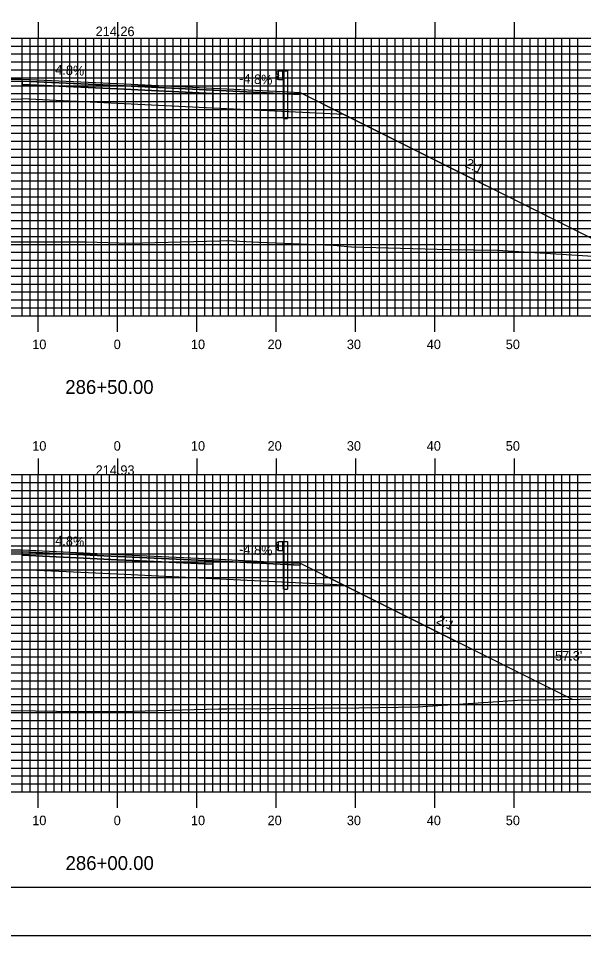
# Model space of a CAD drawing. Extents: x 1812554 to 1812897, y 442591 to 442811.
# Drawn here: x 1812707.4 to 1812778.7, y 442590.5 to 442706.2 of the extents above; entities that cross this region are included whole.
import ezdxf

# ---------------------------------------------------------------- set-up
doc = ezdxf.new("R2010")
doc.units = 0
for name, color, linetype in [('ANNOTATION', 7, 'Continuous'), ('BORDER', 7, 'Continuous'), ('D_Guardrail_Beam_Rt', 7, 'Continuous'), ('D_Roadway_Centerline', 7, 'Continuous'), ('D_Roadway_Centerline_Text', 7, 'Continuous'), ('D_Roadway_Edge_Shoulder', 7, 'Continuous'), ('D_Roadway_Edge_TW', 7, 'Continuous'), ('D_Roadway_Pavement', 7, 'Continuous'), ('D_Roadway_SlopeLines', 7, 'Continuous'), ('D_Roadway_SubGrade', 7, 'Continuous'), ('D_Text_Standard', 7, 'Continuous'), ('H_V ANNOTATION', 7, 'Continuous'), ('MAJOR', 7, 'Continuous'), ('MINOR', 7, 'Continuous'), ('PLOT BOUNDARY', 7, 'Continuous'), ('S_Roadway_Centerline', 7, 'Continuous')]:
    doc.layers.add(name, color=color, linetype=linetype)

msp = doc.modelspace()

# ---------------------------------------------------------------- linework, layer by layer
at = {"layer": 'BORDER'}
msp.add_lwpolyline([(1812570.34, 442596.67), (1812890.34, 442596.67), (1812890.34, 442806.67), (1812570.34, 442806.67)], close=True, dxfattribs=at)
at = {"layer": 'D_Guardrail_Beam_Rt'}
for p, q in [((1812740.12, 442699.45), (1812739.98, 442699.35)), ((1812740.21, 442699.47), (1812740.14, 442699.45)), ((1812740.21, 442699.55), (1812740.9, 442699.55)), ((1812740.21, 442698.39), (1812740.21, 442699.55)), ((1812740.73, 442699.55), (1812740.73, 442698.39)), ((1812740.84, 442699.55), (1812740.84, 442698.39)), ((1812740.9, 442699.55), (1812741.37, 442699.55)), ((1812740.9, 442699.55), (1812740.9, 442698.39)), ((1812741.37, 442699.55), (1812741.37, 442693.55)), ((1812739.98, 442699.2), (1812740.17, 442699.07)), ((1812740.17, 442698.87), (1812739.98, 442698.73)), ((1812739.98, 442698.59), (1812740.12, 442698.49)), ((1812740.14, 442698.48), (1812740.21, 442698.47)), ((1812740.21, 442699), (1812740.21, 442698.93)), ((1812740.9, 442698.39), (1812740.21, 442698.39)), ((1812740.88, 442693.55), (1812740.88, 442698.39)), ((1812740.88, 442693.55), (1812741.37, 442693.55)), ((1812740.12, 442640.11), (1812739.98, 442640.01)), ((1812739.98, 442639.87), (1812740.17, 442639.73)), ((1812740.17, 442639.53), (1812739.98, 442639.4)), ((1812740.21, 442640.13), (1812740.14, 442640.12)), ((1812740.21, 442640.22), (1812740.9, 442640.22)), ((1812740.21, 442639.05), (1812740.21, 442640.22)), ((1812740.21, 442639.67), (1812740.21, 442639.6)), ((1812740.73, 442640.22), (1812740.73, 442639.05)), ((1812740.84, 442640.22), (1812740.84, 442639.05)), ((1812740.9, 442640.22), (1812741.37, 442640.22)), ((1812740.9, 442640.22), (1812740.9, 442639.05)), ((1812741.37, 442640.22), (1812741.37, 442634.22)), ((1812739.98, 442639.25), (1812740.12, 442639.15)), ((1812740.14, 442639.15), (1812740.21, 442639.13)), ((1812740.9, 442639.05), (1812740.21, 442639.05)), ((1812740.88, 442634.22), (1812740.88, 442639.05)), ((1812740.88, 442634.22), (1812741.37, 442634.22))]:
    msp.add_line(p, q, dxfattribs=at)
for centre, major_axis, start_param, end_param in [((1812740.15, 442699.41), (-0.0417, 0), 4.907132, 5.323254), ((1812740.03, 442699.28), (-0.0877, 0), 5.323254, 7.243116), ((1812740.03, 442698.66), (-0.0877, 0), 5.323254, 7.243116), ((1812740.15, 442698.52), (-0.0417, 0), 0.959931, 1.376053), ((1812740.13, 442699), (0.0789, 0), 0, 0.959931), ((1812740.13, 442698.93), (0.0789, 0), 5.323254, 6.283185), ((1812740.03, 442639.94), (-0.0877, 0), 5.323254, 7.243116), ((1812740.03, 442639.33), (-0.0877, 0), 5.323254, 7.243116), ((1812740.15, 442640.08), (-0.0417, 0), 4.907132, 5.323254), ((1812740.13, 442639.67), (0.0789, 0), 0, 0.959931), ((1812740.13, 442639.6), (0.0789, 0), 5.323254, 6.283185), ((1812740.15, 442639.19), (-0.0417, 0), 0.959931, 1.376053)]:
    msp.add_ellipse(centre, major_axis=major_axis, ratio=0.995501, start_param=start_param, end_param=end_param, dxfattribs=at)
at = {"layer": 'D_Roadway_Centerline'}
for points in [[(1812656.82, 442678.23), (1812691.73, 442695.68), (1812696.94, 442698.28), (1812699.94, 442698.34), (1812707.94, 442698.5), (1812719.94, 442697.93), (1812731.94, 442697.35), (1812739.94, 442696.97), (1812742.94, 442696.82), (1812748.47, 442694.06), (1812784.48, 442676.06)], [(1812656.53, 442618.74), (1812691.73, 442636.34), (1812696.94, 442638.95), (1812699.94, 442639.01), (1812707.94, 442639.17), (1812719.94, 442638.59), (1812731.94, 442638.02), (1812739.94, 442637.63), (1812742.94, 442637.49), (1812748.47, 442634.72), (1812777.24, 442620.34)]]:
    msp.add_lwpolyline(points, dxfattribs=at)
at = {"layer": 'D_Roadway_Edge_Shoulder'}
for points in [[(1812707.94, 442698.5), (1812699.94, 442698.34), (1812699.94, 442698.34), (1812696.94, 442698.28), (1812696.94, 442698.03), (1812707.94, 442698.25)], [(1812731.94, 442697.35), (1812739.94, 442696.97), (1812739.94, 442696.97), (1812742.94, 442696.82), (1812742.94, 442696.57), (1812731.94, 442697.1)], [(1812707.94, 442639.17), (1812699.94, 442639.01), (1812699.94, 442639.01), (1812696.94, 442638.95), (1812696.94, 442638.7), (1812707.94, 442638.92)], [(1812731.94, 442638.02), (1812739.94, 442637.63), (1812739.94, 442637.63), (1812742.94, 442637.49), (1812742.94, 442637.24), (1812731.94, 442637.77)]]:
    msp.add_lwpolyline(points, close=True, dxfattribs=at)
at = {"layer": 'D_Roadway_Edge_TW'}
for points in [[(1812707.94, 442698.25), (1812707.94, 442698.5), (1812719.94, 442697.93), (1812731.94, 442697.35), (1812731.94, 442697.1), (1812719.94, 442697.68)], [(1812707.94, 442638.92), (1812707.94, 442639.17), (1812719.94, 442638.59), (1812731.94, 442638.02), (1812731.94, 442637.77), (1812719.94, 442638.34)]]:
    msp.add_lwpolyline(points, close=True, dxfattribs=at)
at = {"layer": 'D_Roadway_Pavement'}
for points in [[(1812707.94, 442697.84), (1812707.94, 442698.25), (1812719.94, 442697.68), (1812731.94, 442697.1), (1812731.94, 442696.69), (1812719.94, 442697.26)], [(1812707.94, 442638.5), (1812707.94, 442638.92), (1812719.94, 442638.34), (1812731.94, 442637.77), (1812731.94, 442637.35), (1812719.94, 442637.93)]]:
    msp.add_lwpolyline(points, close=True, dxfattribs=at)
for points in [[(1812707.94, 442698.25), (1812707.94, 442697.84)], [(1812731.94, 442697.1), (1812731.94, 442696.69)], [(1812707.94, 442638.92), (1812707.94, 442638.5)], [(1812731.94, 442637.77), (1812731.94, 442637.35)]]:
    msp.add_lwpolyline(points, dxfattribs=at)
at = {"layer": 'D_Roadway_SlopeLines'}
for points in [[(1812742.94, 442696.82), (1812784.48, 442676.06)], [(1812742.94, 442637.49), (1812777.24, 442620.34)]]:
    msp.add_lwpolyline(points, dxfattribs=at)
at = {"layer": 'D_Roadway_SubGrade'}
for points in [[(1812707.94, 442697.84), (1812707.94, 442698.25), (1812696.94, 442698.03), (1812696.94, 442698.28), (1812691.73, 442695.68), (1812707.94, 442696)], [(1812707.94, 442696), (1812707.94, 442698.25), (1812707.94, 442697.84), (1812719.94, 442697.26), (1812731.94, 442696.69), (1812731.94, 442697.1), (1812731.94, 442694.85), (1812719.94, 442695.43)], [(1812731.94, 442696.69), (1812731.94, 442697.1), (1812742.94, 442696.57), (1812742.94, 442696.82), (1812748.47, 442694.06), (1812731.94, 442694.85)], [(1812707.94, 442638.5), (1812707.94, 442638.92), (1812696.94, 442638.7), (1812696.94, 442638.95), (1812691.73, 442636.34), (1812707.94, 442636.67)], [(1812707.94, 442636.67), (1812707.94, 442638.92), (1812707.94, 442638.5), (1812719.94, 442637.93), (1812731.94, 442637.35), (1812731.94, 442637.77), (1812731.94, 442635.52), (1812719.94, 442636.09)], [(1812731.94, 442637.35), (1812731.94, 442637.77), (1812742.94, 442637.24), (1812742.94, 442637.49), (1812748.47, 442634.72), (1812731.94, 442635.52)]]:
    msp.add_lwpolyline(points, close=True, dxfattribs=at)
at = {"layer": 'MAJOR'}
for p, q in [((1812709.94, 442705.67), (1812709.94, 442703.67)), ((1812719.94, 442705.67), (1812719.94, 442703.67)), ((1812729.94, 442705.67), (1812729.94, 442703.67)), ((1812739.94, 442705.67), (1812739.94, 442703.67)), ((1812749.94, 442705.67), (1812749.94, 442703.67)), ((1812759.94, 442705.67), (1812759.94, 442703.67)), ((1812769.94, 442705.67), (1812769.94, 442703.67)), ((1812579.94, 442703.67), (1812859.94, 442703.67)), ((1812579.94, 442703.67), (1812859.94, 442703.67)), ((1812709.94, 442668.67), (1812709.94, 442703.67)), ((1812719.94, 442668.67), (1812719.94, 442703.67)), ((1812729.94, 442668.67), (1812729.94, 442703.67)), ((1812739.94, 442668.67), (1812739.94, 442703.67)), ((1812749.94, 442668.67), (1812749.94, 442703.67)), ((1812759.94, 442668.67), (1812759.94, 442703.67)), ((1812769.94, 442668.67), (1812769.94, 442703.67)), ((1812579.94, 442698.67), (1812859.94, 442698.67)), ((1812579.94, 442693.67), (1812859.94, 442693.67)), ((1812579.94, 442688.67), (1812859.94, 442688.67)), ((1812579.94, 442683.67), (1812859.94, 442683.67)), ((1812579.94, 442678.67), (1812859.94, 442678.67)), ((1812579.94, 442673.67), (1812859.94, 442673.67)), ((1812579.94, 442668.67), (1812859.94, 442668.67)), ((1812579.94, 442668.67), (1812859.94, 442668.67)), ((1812709.94, 442666.66), (1812709.94, 442668.67)), ((1812719.94, 442666.66), (1812719.94, 442668.67)), ((1812729.94, 442666.66), (1812729.94, 442668.67)), ((1812739.94, 442666.66), (1812739.94, 442668.67)), ((1812749.94, 442666.66), (1812749.94, 442668.67)), ((1812759.94, 442666.66), (1812759.94, 442668.67)), ((1812769.94, 442666.66), (1812769.94, 442668.67)), ((1812709.94, 442650.67), (1812709.94, 442648.67)), ((1812719.94, 442650.67), (1812719.94, 442648.67)), ((1812729.94, 442650.67), (1812729.94, 442648.67)), ((1812739.94, 442650.67), (1812739.94, 442648.67)), ((1812749.94, 442650.67), (1812749.94, 442648.67)), ((1812759.94, 442650.67), (1812759.94, 442648.67)), ((1812769.94, 442650.67), (1812769.94, 442648.67)), ((1812579.94, 442648.67), (1812859.94, 442648.67)), ((1812579.94, 442648.67), (1812859.94, 442648.67)), ((1812709.94, 442608.67), (1812709.94, 442648.67)), ((1812719.94, 442608.67), (1812719.94, 442648.67)), ((1812729.94, 442608.67), (1812729.94, 442648.67)), ((1812739.94, 442608.67), (1812739.94, 442648.67)), ((1812749.94, 442608.67), (1812749.94, 442648.67)), ((1812759.94, 442608.67), (1812759.94, 442648.67)), ((1812769.94, 442608.67), (1812769.94, 442648.67)), ((1812579.94, 442643.67), (1812859.94, 442643.67)), ((1812579.94, 442638.67), (1812859.94, 442638.67)), ((1812579.94, 442633.67), (1812859.94, 442633.67)), ((1812579.94, 442628.67), (1812859.94, 442628.67)), ((1812579.94, 442623.67), (1812859.94, 442623.67)), ((1812579.94, 442618.67), (1812859.94, 442618.67)), ((1812579.94, 442613.67), (1812859.94, 442613.67)), ((1812579.94, 442608.67), (1812859.94, 442608.67)), ((1812579.94, 442608.67), (1812859.94, 442608.67)), ((1812709.94, 442606.66), (1812709.94, 442608.67)), ((1812719.94, 442606.66), (1812719.94, 442608.67)), ((1812729.94, 442606.66), (1812729.94, 442608.67)), ((1812739.94, 442606.66), (1812739.94, 442608.67)), ((1812749.94, 442606.66), (1812749.94, 442608.67)), ((1812759.94, 442606.66), (1812759.94, 442608.67)), ((1812769.94, 442606.66), (1812769.94, 442608.67))]:
    msp.add_line(p, q, dxfattribs=at)
at = {"layer": 'MINOR'}
for p, q in [((1812707.94, 442668.67), (1812707.94, 442703.67)), ((1812708.94, 442668.67), (1812708.94, 442703.67)), ((1812710.94, 442668.67), (1812710.94, 442703.67)), ((1812711.94, 442668.67), (1812711.94, 442703.67)), ((1812712.94, 442668.67), (1812712.94, 442703.67)), ((1812713.94, 442668.67), (1812713.94, 442703.67)), ((1812714.94, 442668.67), (1812714.94, 442703.67)), ((1812715.94, 442668.67), (1812715.94, 442703.67)), ((1812716.94, 442668.67), (1812716.94, 442703.67)), ((1812717.94, 442668.67), (1812717.94, 442703.67)), ((1812718.94, 442668.67), (1812718.94, 442703.67)), ((1812720.94, 442668.67), (1812720.94, 442703.67)), ((1812721.94, 442668.67), (1812721.94, 442703.67)), ((1812722.94, 442668.67), (1812722.94, 442703.67)), ((1812723.94, 442668.67), (1812723.94, 442703.67)), ((1812724.94, 442668.67), (1812724.94, 442703.67)), ((1812725.94, 442668.67), (1812725.94, 442703.67)), ((1812726.94, 442668.67), (1812726.94, 442703.67)), ((1812727.94, 442668.67), (1812727.94, 442703.67)), ((1812728.94, 442668.67), (1812728.94, 442703.67)), ((1812730.94, 442668.67), (1812730.94, 442703.67)), ((1812731.94, 442668.67), (1812731.94, 442703.67)), ((1812732.94, 442668.67), (1812732.94, 442703.67)), ((1812733.94, 442668.67), (1812733.94, 442703.67)), ((1812734.94, 442668.67), (1812734.94, 442703.67)), ((1812735.94, 442668.67), (1812735.94, 442703.67)), ((1812736.94, 442668.67), (1812736.94, 442703.67)), ((1812737.94, 442668.67), (1812737.94, 442703.67)), ((1812738.94, 442668.67), (1812738.94, 442703.67)), ((1812740.94, 442668.67), (1812740.94, 442703.67)), ((1812741.94, 442668.67), (1812741.94, 442703.67)), ((1812742.94, 442668.67), (1812742.94, 442703.67)), ((1812743.94, 442668.67), (1812743.94, 442703.67)), ((1812744.94, 442668.67), (1812744.94, 442703.67)), ((1812745.94, 442668.67), (1812745.94, 442703.67)), ((1812746.94, 442668.67), (1812746.94, 442703.67)), ((1812747.94, 442668.67), (1812747.94, 442703.67)), ((1812748.94, 442668.67), (1812748.94, 442703.67)), ((1812750.94, 442668.67), (1812750.94, 442703.67)), ((1812751.94, 442668.67), (1812751.94, 442703.67)), ((1812752.94, 442668.67), (1812752.94, 442703.67)), ((1812753.94, 442668.67), (1812753.94, 442703.67)), ((1812754.94, 442668.67), (1812754.94, 442703.67)), ((1812755.94, 442668.67), (1812755.94, 442703.67)), ((1812756.94, 442668.67), (1812756.94, 442703.67)), ((1812757.94, 442668.67), (1812757.94, 442703.67)), ((1812758.94, 442668.67), (1812758.94, 442703.67)), ((1812760.94, 442668.67), (1812760.94, 442703.67)), ((1812761.94, 442668.67), (1812761.94, 442703.67)), ((1812762.94, 442668.67), (1812762.94, 442703.67)), ((1812763.94, 442668.67), (1812763.94, 442703.67)), ((1812764.94, 442668.67), (1812764.94, 442703.67)), ((1812765.94, 442668.67), (1812765.94, 442703.67)), ((1812766.94, 442668.67), (1812766.94, 442703.67)), ((1812767.94, 442668.67), (1812767.94, 442703.67)), ((1812768.94, 442668.67), (1812768.94, 442703.67)), ((1812770.94, 442668.67), (1812770.94, 442703.67)), ((1812771.94, 442668.67), (1812771.94, 442703.67)), ((1812772.94, 442668.67), (1812772.94, 442703.67)), ((1812773.94, 442668.67), (1812773.94, 442703.67)), ((1812774.94, 442668.67), (1812774.94, 442703.67)), ((1812775.94, 442668.67), (1812775.94, 442703.67)), ((1812776.94, 442668.67), (1812776.94, 442703.67)), ((1812777.94, 442668.67), (1812777.94, 442703.67)), ((1812579.94, 442702.67), (1812859.94, 442702.67)), ((1812579.94, 442701.67), (1812859.94, 442701.67)), ((1812579.94, 442700.67), (1812859.94, 442700.67)), ((1812579.94, 442699.67), (1812859.94, 442699.67)), ((1812579.94, 442697.67), (1812859.94, 442697.67)), ((1812579.94, 442696.67), (1812859.94, 442696.67)), ((1812579.94, 442695.67), (1812859.94, 442695.67)), ((1812579.94, 442694.67), (1812859.94, 442694.67)), ((1812579.94, 442692.67), (1812859.94, 442692.67)), ((1812579.94, 442691.67), (1812859.94, 442691.67)), ((1812579.94, 442690.67), (1812859.94, 442690.67)), ((1812579.94, 442689.67), (1812859.94, 442689.67)), ((1812579.94, 442687.67), (1812859.94, 442687.67)), ((1812579.94, 442686.67), (1812859.94, 442686.67)), ((1812579.94, 442685.67), (1812859.94, 442685.67)), ((1812579.94, 442684.67), (1812859.94, 442684.67)), ((1812579.94, 442682.67), (1812859.94, 442682.67)), ((1812579.94, 442681.67), (1812859.94, 442681.67)), ((1812579.94, 442680.67), (1812859.94, 442680.67)), ((1812579.94, 442679.67), (1812859.94, 442679.67)), ((1812579.94, 442677.67), (1812859.94, 442677.67)), ((1812579.94, 442676.67), (1812859.94, 442676.67)), ((1812579.94, 442675.67), (1812859.94, 442675.67)), ((1812579.94, 442674.67), (1812859.94, 442674.67)), ((1812579.94, 442672.67), (1812859.94, 442672.67)), ((1812579.94, 442671.67), (1812859.94, 442671.67)), ((1812579.94, 442670.67), (1812859.94, 442670.67)), ((1812579.94, 442669.67), (1812859.94, 442669.67)), ((1812707.94, 442608.67), (1812707.94, 442648.67)), ((1812708.94, 442608.67), (1812708.94, 442648.67)), ((1812710.94, 442608.67), (1812710.94, 442648.67)), ((1812711.94, 442608.67), (1812711.94, 442648.67)), ((1812712.94, 442608.67), (1812712.94, 442648.67)), ((1812713.94, 442608.67), (1812713.94, 442648.67)), ((1812714.94, 442608.67), (1812714.94, 442648.67)), ((1812715.94, 442608.67), (1812715.94, 442648.67)), ((1812716.94, 442608.67), (1812716.94, 442648.67)), ((1812717.94, 442608.67), (1812717.94, 442648.67)), ((1812718.94, 442608.67), (1812718.94, 442648.67)), ((1812720.94, 442608.67), (1812720.94, 442648.67)), ((1812721.94, 442608.67), (1812721.94, 442648.67)), ((1812722.94, 442608.67), (1812722.94, 442648.67)), ((1812723.94, 442608.67), (1812723.94, 442648.67)), ((1812724.94, 442608.67), (1812724.94, 442648.67)), ((1812725.94, 442608.67), (1812725.94, 442648.67)), ((1812726.94, 442608.67), (1812726.94, 442648.67)), ((1812727.94, 442608.67), (1812727.94, 442648.67)), ((1812728.94, 442608.67), (1812728.94, 442648.67)), ((1812730.94, 442608.67), (1812730.94, 442648.67)), ((1812731.94, 442608.67), (1812731.94, 442648.67)), ((1812732.94, 442608.67), (1812732.94, 442648.67)), ((1812733.94, 442608.67), (1812733.94, 442648.67)), ((1812734.94, 442608.67), (1812734.94, 442648.67)), ((1812735.94, 442608.67), (1812735.94, 442648.67)), ((1812736.94, 442608.67), (1812736.94, 442648.67)), ((1812737.94, 442608.67), (1812737.94, 442648.67)), ((1812738.94, 442608.67), (1812738.94, 442648.67)), ((1812740.94, 442608.67), (1812740.94, 442648.67)), ((1812741.94, 442608.67), (1812741.94, 442648.67)), ((1812742.94, 442608.67), (1812742.94, 442648.67)), ((1812743.94, 442608.67), (1812743.94, 442648.67)), ((1812744.94, 442608.67), (1812744.94, 442648.67)), ((1812745.94, 442608.67), (1812745.94, 442648.67)), ((1812746.94, 442608.67), (1812746.94, 442648.67)), ((1812747.94, 442608.67), (1812747.94, 442648.67)), ((1812748.94, 442608.67), (1812748.94, 442648.67)), ((1812750.94, 442608.67), (1812750.94, 442648.67)), ((1812751.94, 442608.67), (1812751.94, 442648.67)), ((1812752.94, 442608.67), (1812752.94, 442648.67)), ((1812753.94, 442608.67), (1812753.94, 442648.67)), ((1812754.94, 442608.67), (1812754.94, 442648.67)), ((1812755.94, 442608.67), (1812755.94, 442648.67)), ((1812756.94, 442608.67), (1812756.94, 442648.67)), ((1812757.94, 442608.67), (1812757.94, 442648.67)), ((1812758.94, 442608.67), (1812758.94, 442648.67)), ((1812760.94, 442608.67), (1812760.94, 442648.67)), ((1812761.94, 442608.67), (1812761.94, 442648.67)), ((1812762.94, 442608.67), (1812762.94, 442648.67)), ((1812763.94, 442608.67), (1812763.94, 442648.67)), ((1812764.94, 442608.67), (1812764.94, 442648.67)), ((1812765.94, 442608.67), (1812765.94, 442648.67)), ((1812766.94, 442608.67), (1812766.94, 442648.67)), ((1812767.94, 442608.67), (1812767.94, 442648.67)), ((1812768.94, 442608.67), (1812768.94, 442648.67)), ((1812770.94, 442608.67), (1812770.94, 442648.67)), ((1812771.94, 442608.67), (1812771.94, 442648.67)), ((1812772.94, 442608.67), (1812772.94, 442648.67)), ((1812773.94, 442608.67), (1812773.94, 442648.67)), ((1812774.94, 442608.67), (1812774.94, 442648.67)), ((1812775.94, 442608.67), (1812775.94, 442648.67)), ((1812776.94, 442608.67), (1812776.94, 442648.67)), ((1812777.94, 442608.67), (1812777.94, 442648.67)), ((1812579.94, 442647.67), (1812859.94, 442647.67)), ((1812579.94, 442646.67), (1812859.94, 442646.67)), ((1812579.94, 442645.67), (1812859.94, 442645.67)), ((1812579.94, 442644.67), (1812859.94, 442644.67)), ((1812579.94, 442642.67), (1812859.94, 442642.67)), ((1812579.94, 442641.67), (1812859.94, 442641.67)), ((1812579.94, 442640.67), (1812859.94, 442640.67)), ((1812579.94, 442639.67), (1812859.94, 442639.67)), ((1812579.94, 442637.67), (1812859.94, 442637.67)), ((1812579.94, 442636.67), (1812859.94, 442636.67)), ((1812579.94, 442635.67), (1812859.94, 442635.67)), ((1812579.94, 442634.67), (1812859.94, 442634.67)), ((1812579.94, 442632.67), (1812859.94, 442632.67)), ((1812579.94, 442631.67), (1812859.94, 442631.67)), ((1812579.94, 442630.67), (1812859.94, 442630.67)), ((1812579.94, 442629.67), (1812859.94, 442629.67)), ((1812579.94, 442627.67), (1812859.94, 442627.67)), ((1812579.94, 442626.67), (1812859.94, 442626.67)), ((1812579.94, 442625.67), (1812859.94, 442625.67)), ((1812579.94, 442624.67), (1812859.94, 442624.67)), ((1812579.94, 442622.67), (1812859.94, 442622.67)), ((1812579.94, 442621.67), (1812859.94, 442621.67)), ((1812579.94, 442620.67), (1812859.94, 442620.67)), ((1812579.94, 442619.67), (1812859.94, 442619.67)), ((1812579.94, 442617.67), (1812859.94, 442617.67)), ((1812579.94, 442616.67), (1812859.94, 442616.67)), ((1812579.94, 442615.67), (1812859.94, 442615.67)), ((1812579.94, 442614.67), (1812859.94, 442614.67)), ((1812579.94, 442612.67), (1812859.94, 442612.67)), ((1812579.94, 442611.67), (1812859.94, 442611.67)), ((1812579.94, 442610.67), (1812859.94, 442610.67)), ((1812579.94, 442609.67), (1812859.94, 442609.67))]:
    msp.add_line(p, q, dxfattribs=at)
at = {"layer": 'PLOT BOUNDARY'}
msp.add_lwpolyline([(1812554.16, 442590.55), (1812894.16, 442590.55), (1812894.16, 442810.55), (1812554.16, 442810.55)], close=True, dxfattribs=at)
at = {"layer": 'S_Roadway_Centerline'}
for points in [[(1812653.73, 442678.2), (1812664.05, 442678.28), (1812670.2, 442678.03), (1812681.46, 442678.56), (1812681.74, 442678.57), (1812683.25, 442678.52), (1812695.85, 442678.12), (1812698.51, 442678.03), (1812703.64, 442678.01), (1812716.05, 442678), (1812721.43, 442677.84), (1812732.8, 442678.11), (1812733.7, 442678.15), (1812737.73, 442677.96), (1812747.15, 442677.59), (1812749.41, 442677.36), (1812761.79, 442677.03), (1812767.82, 442676.93), (1812779.87, 442676.18)], [(1812650.1, 442618.55), (1812669.43, 442619.14), (1812680.46, 442618.84), (1812682.07, 442618.84), (1812698.91, 442618.79), (1812706.9, 442618.91), (1812714.95, 442618.78), (1812720.34, 442618.78), (1812731.14, 442619.09), (1812732.66, 442619.12), (1812733.73, 442619.12), (1812750.36, 442619.27), (1812757.81, 442619.39), (1812767.9, 442620.07), (1812770.37, 442620.21), (1812780.84, 442620.41)]]:
    msp.add_lwpolyline(points, dxfattribs=at)

# ---------------------------------------------------------------- texts
at = {"layer": 'ANNOTATION'}
for s, rotation, p in [('4.8%', 357.2519, (1812712.07, 442699.11)), ('-4.8%', 357.2519, (1812735.25, 442698)), ('2:1', 333.4349, (1812763.64, 442687.51)), ('4.8%', 357.2519, (1812712.07, 442639.77)), ('-4.8%', 357.2519, (1812735.25, 442638.66)), ('2:1', 333.4349, (1812760.03, 442629.98))]:
    msp.add_text(s, height=1.2, rotation=rotation, dxfattribs=at).set_placement(p)
at = {"layer": 'D_Roadway_Centerline'}
for s, p in [('C', (1812719.94, 442697.93)), ('L', (1812719.94, 442697.92)), ('C', (1812719.94, 442638.59)), ('L', (1812719.94, 442638.59))]:
    msp.add_text(s, height=0.0146, dxfattribs=at).set_placement(p)
at = {"layer": 'D_Roadway_Centerline_Text'}
for s, p in [('214.26', (1812717.18, 442703.92)), ('214.93', (1812717.18, 442648.62))]:
    msp.add_text(s, height=1.2, dxfattribs=at).set_placement(p)
at = {"layer": 'D_Text_Standard'}
msp.add_text("57.3'", height=1.2, dxfattribs=at).set_placement((1812775.08, 442625.22))
at = {"layer": 'H_V ANNOTATION'}
for s, height, p in [('10', 1.2, (1812709.19, 442664.47)), ('0', 1.2, (1812719.46, 442664.47)), ('10', 1.2, (1812729.19, 442664.47)), ('20', 1.2, (1812738.85, 442664.47)), ('30', 1.2, (1812748.84, 442664.47)), ('40', 1.2, (1812758.91, 442664.47)), ('50', 1.2, (1812768.87, 442664.47)), ('286+50.00', 1.75, (1812713.36, 442658.82)), ('10', 1.2, (1812709.19, 442651.67)), ('0', 1.2, (1812719.46, 442651.67)), ('10', 1.2, (1812729.19, 442651.67)), ('20', 1.2, (1812738.85, 442651.67)), ('30', 1.2, (1812748.84, 442651.67)), ('40', 1.2, (1812758.91, 442651.67)), ('50', 1.2, (1812768.87, 442651.67)), ('10', 1.2, (1812709.19, 442604.47)), ('0', 1.2, (1812719.46, 442604.47)), ('10', 1.2, (1812729.19, 442604.47)), ('20', 1.2, (1812738.85, 442604.47)), ('30', 1.2, (1812748.84, 442604.47)), ('40', 1.2, (1812758.91, 442604.47)), ('50', 1.2, (1812768.87, 442604.47)), ('286+00.00', 1.75, (1812713.39, 442598.82))]:
    msp.add_text(s, height=height, dxfattribs=at).set_placement(p)

doc.saveas('drawing.dxf')
